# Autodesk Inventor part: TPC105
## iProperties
Shininess: 64.0
Length Units: 11272
Angle Units: 11279
Time Units: 11290
Mass Units: 11286
Length Display Precision: 3
Angle Display Precision: 2
Compacted: True
Part Number: TPC105
Document SubType Name: Modeling
Created: 2004-08
Designer: Lori
Manufacturer: Standard
Standards Organization: Custom
Density: 0.0
Volumn: 0.0
Area: 0.0
PropertySet Name: Model Information
Control State: 0
Master: False
Checked Out: False
Author: Lori
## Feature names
1. Base1
